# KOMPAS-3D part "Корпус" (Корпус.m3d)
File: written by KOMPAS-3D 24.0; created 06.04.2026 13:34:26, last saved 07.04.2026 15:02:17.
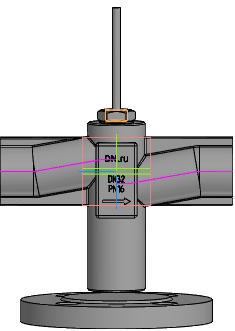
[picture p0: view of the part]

Document properties: Автор: R2D2; Полное имя файла: E:\Работа\Зайцев\Солянка\VSR1-13V-PED-F Клапан запорно-регулирующий DN.ru\DN32\исходные материалы\Корпус.m3d

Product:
- Body: Труба / Нестандартная труба / L = 85.8 мм  | qty 1
    Материал: Нестандартная труба (density 7856 kg/m3)
    Масса: 2.660699
    Раздел спецификации: Детали
    Примечание: 0,72 кг
    additional columns: Pipeline; 0.037; 0; 0; 0.002; 0.08577; true; 0.04
- Body: Труба / Нестандартная труба / L = 85.8 мм  | qty 1
    Материал: Нестандартная труба (density 7856 kg/m3)
    Масса: 2.660699
    Раздел спецификации: Детали
    Форматы листов документа: БЧ
    Примечание: 0,72 кг
    additional columns: Pipeline; 0.037; 0; 0; 0.002; 0.08577; true; 0.04
- Component [standard]: Гайка М16-6H ГОСТ 5916-70  | qty 1  | Масса: 0.01768; Рассекать на разрезах: no; source file: C:\Program Files\ASCON\KOMPAS-3D v24\Libs\PolynomLib\DATA\vault\Methods\Kompas\3D\PLib_Nut_OST92_900.m3d
- Component [standard]: (unnamed)  | qty 1  | Материал: ВЧ40 ГОСТ 7293-85 (density 7200 kg/m3); Масса: 1.728504; Рассекать на разрезах: no; additional columns: 32-16-B-2-ВЧ40-II; Заглушка; ГОСТ 34785-2021
- Body: Тело 4  | qty 1
    Материал: Нестандартная труба (density 7856 kg/m3)
    Масса: 2.660699
- Part/product: Корпус
    Масса: 6.9

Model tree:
1. Эскиз:1
2. Труба:1  (labels: {F703FF30-5BE6-4673-A7F1-8EDA1BE1E2D1}; SHAPEOBJECT3D_ATTR_BUTT; SHAPEOBJECT3D_ATTR_VALID; SHAPEOBJECT3D_ATTR_BUTT_AREA)
     PIPE_R = 7
3. Труба:2  (labels: {F703FF30-5BE6-4673-A7F1-8EDA1BE1E2D1}; SHAPEOBJECT3D_ATTR_BUTT; SHAPEOBJECT3D_ATTR_VALID; SHAPEOBJECT3D_ATTR_BUTT_AREA)
     PIPE_R = 7
4. Эскиз:2
5. Элемент выдавливания:1
     Расстояние 1 = 36; Смещение 1 = -1; Расстояние 2 = 87; Смещение 2 = -5
6. РЕБРО  (with: Ребро.Труба:2)
7. Элемент выдавливания:2
     Расстояние 1 = 6
8. Эскиз:4  (with: Грань.Элемент выдавливания:1)
9. Скругление:3  (with: Ребро.Элемент выдавливания:2)
10. Элемент выдавливания:3
     Расстояние 1 = 1
11. Эскиз:5  (with: Грань.Элемент выдавливания:3)
12. Элемент выдавливания:4
     Расстояние 1 = 7.5; Смещение 1 = 0.5
13. ШТОК
14. Элемент выдавливания:5
15. ОТЛИВКА
16. Скругление:6  (with: Грань.Элемент выдавливания:1)
17. Элемент выдавливания:6  (with: Грань.Элемент выдавливания:1)
     Смещение 1 = 4
18. Эскиз:8  (with: Грань.Элемент выдавливания:6)
19. Элемент выдавливания:7
     Расстояние 1 = 0.5
20. Скругление:7  (with: Ребро.Элемент выдавливания:6, Грань.Элемент выдавливания:3)
     Радиус = 2

Expressions: DS/2+3
Referenced files in C:\Program Files\ASCON\KOMPAS-3D v24\Libs\Pipeline\: StylesTemplate.a3d, TemplateHPH, InsulationStylesTemplate.a3d, Insulation
Referenced files in C:\Program Files\ASCON\KOMPAS-3D v24\Templates\: Констр. чертеж А3 гориз. перв. лист.cdt
Referenced files in E:\Работа\Зайцев\Солянка\VSR1-13V-PED-F Клапан запорно-регулирующий DN.ru\DN15\DN15 Kv0.16\исходные материалы\: 
Referenced files in C:\Program Files\ASCON\KOMPAS-3D v24\Libs\PolynomLib\DATA\vault\Methods\Kompas\3D\: PLib_Nut_OST92_900.m3d, PLib_Flange_Blind_GOST_34785_2100.m3d
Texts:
  Отводы ГОСТ 17375-2001
  Констр. чертеж А3 гориз. перв. лист.cdt
  BOSimple***PART:2c8e7818-1586-f79e-db7d-bc045ba468e4***SHORTLOC:Root±30±10±20±©{}110±10±50±80[Нет;Без покрытия;Без указания материала;-;16;2;24]
  BOSimple***Material:38d6725a-5efe-48e1-b177-a7817acb862a
  BOSimple***PART:619e43b4-98e6-48f0-940d-c67d37cea500***SHORTLOC:B619_EF039B503CC34112[2;16;32;Круглая;II;ВЧ40 ГОСТ 7293-85]
  var3D
  GOST 2.304 type A
  PN16
  LL-10
  DN+5
  bcut1
  hole1
  hcut1
  hole2
  cut1
  Труба / Нестандартная труба / L = %s мм
  Plane. Начало координат
  Ось Y.Начало координат
  Плоскость ZX.Начало координат
  Плоскость ZY.Начало координат
  Горизонтальная плоскость. Начало координат
  Плоскость XY.Начало координат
